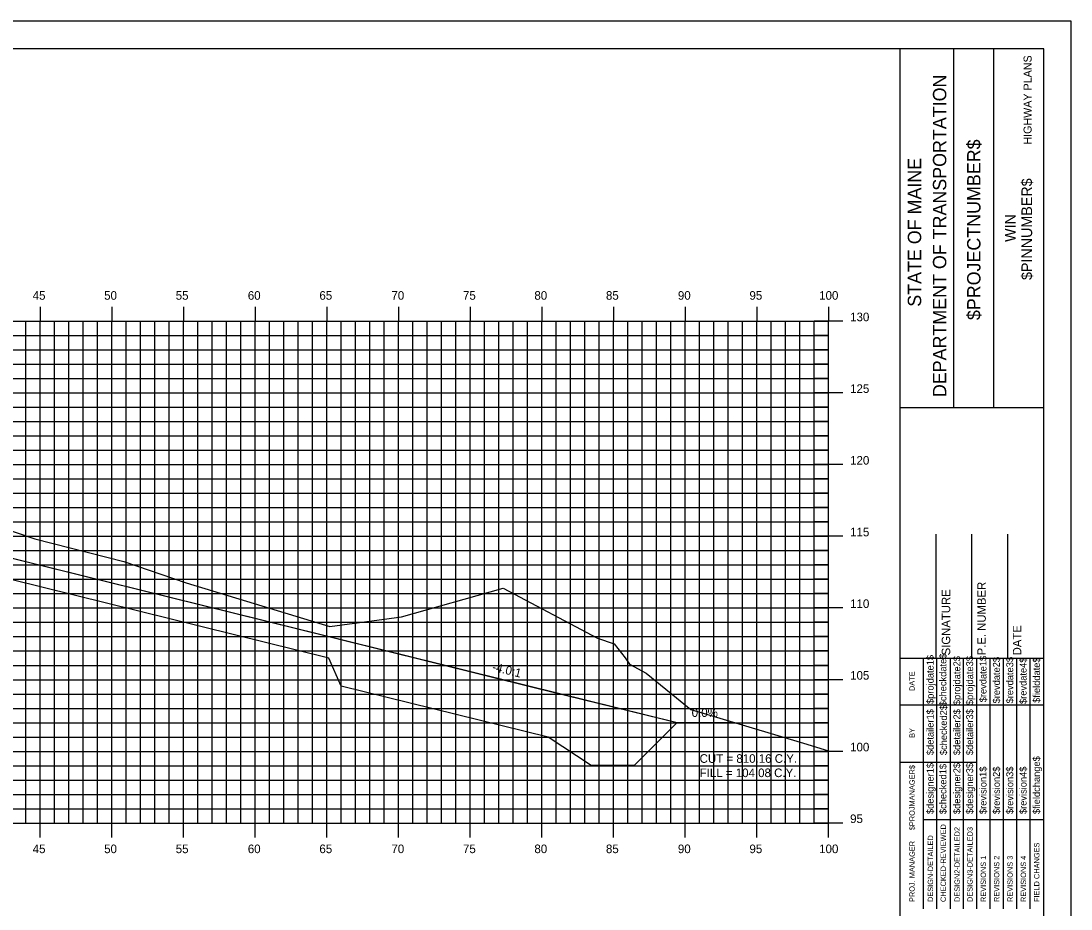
# Model space of a CAD drawing. Extents: x 850598 to 870284, y 366541 to 366651.
# Drawn here: x 859121.3 to 859194.6, y 366589.2 to 366651.2 of the extents above; entities that cross this region are included whole.
import ezdxf

# ---------------------------------------------------------------- set-up
doc = ezdxf.new("R2010")
doc.units = 0
for name, color, linetype in [('ANNOTATION', 7, 'Continuous'), ('BORDER', 7, 'Continuous'), ('D_Drainage_RipRap', 7, 'Continuous'), ('D_Roadway_Centerline', 7, 'Continuous'), ('D_Roadway_SlopeLines', 7, 'Continuous'), ('D_Text_Standard', 7, 'Continuous'), ('H_V ANNOTATION', 7, 'Continuous'), ('HIGHWAY_TITLE', 7, 'Continuous'), ('MAJOR', 7, 'Continuous'), ('MINOR', 7, 'Continuous'), ('PLOT BOUNDARY', 7, 'Continuous'), ('S_Roadway_Centerline', 7, 'Continuous')]:
    doc.layers.add(name, color=color, linetype=linetype)

msp = doc.modelspace()

# ---------------------------------------------------------------- linework, layer by layer
at = {"layer": 'BORDER'}
for p, q in [((859192.646, 366649.225), (859032.646, 366649.225)), ((859182.646, 366544.225), (859182.646, 366649.225)), ((859186.374, 366624.222), (859186.374, 366649.222)), ((859189.169, 366624.222), (859189.169, 366649.222)), ((859192.646, 366544.225), (859192.646, 366649.225)), ((859182.647, 366624.219), (859192.646, 366624.219)), ((859185.146, 366606.728), (859185.146, 366615.376)), ((859187.646, 366606.728), (859187.646, 366615.376)), ((859190.146, 366606.728), (859190.146, 366615.376)), ((859182.646, 366606.728), (859192.646, 366606.728))]:
    msp.add_line(p, q, dxfattribs=at)
for points in [[(859184.261, 366603.478), (859184.261, 366606.728)], [(859185.193, 366589.231), (859185.193, 366606.728)], [(859186.125, 366606.728), (859186.125, 366589.231)], [(859187.057, 366589.231), (859187.057, 366606.728)], [(859187.988, 366589.231), (859187.988, 366606.728)], [(859188.92, 366589.231), (859188.92, 366606.728)], [(859189.852, 366589.231), (859189.852, 366606.728)], [(859190.783, 366589.231), (859190.783, 366606.728)], [(859191.715, 366589.231), (859191.715, 366606.728)], [(859184.262, 366589.231), (859184.262, 366606.022)], [(859182.646, 366603.478), (859192.646, 366603.478)], [(859182.646, 366599.478), (859184.262, 366599.478)], [(859184.261, 366599.478), (859187.987, 366599.478)], [(859184.261, 366595.478), (859192.646, 366595.478)]]:
    msp.add_lwpolyline(points, dxfattribs=at)
at = {"layer": 'D_Drainage_RipRap'}
msp.add_lwpolyline([(859142.79, 366608.23), (859157.209, 366604.667), (859167.071, 366602.23), (859164.071, 366599.23), (859161.071, 366599.23), (859158.071, 366601.217), (859143.652, 366604.78), (859142.79, 366606.73), (859100.646, 366617.144), (859100.646, 366618.644)], close=True, dxfattribs=at)
at = {"layer": 'D_Roadway_Centerline'}
msp.add_lwpolyline([(859050.237, 366616.901), (859055.547, 366618.671), (859061.646, 366620.704), (859066.646, 366621.004), (859077.646, 366621.334), (859088.646, 366621.004), (859092.646, 366620.764), (859094.646, 366620.644), (859100.646, 366618.644), (859142.79, 366608.23), (859157.209, 366604.667), (859167.071, 366602.23), (859171.071, 366602.23)], dxfattribs=at)
at = {"layer": 'D_Roadway_SlopeLines'}
msp.add_lwpolyline([(859100.646, 366618.644), (859167.071, 366602.23), (859167.071, 366602.23)], dxfattribs=at)
at = {"layer": 'MAJOR'}
for p, q in [((859122.646, 366631.227), (859122.646, 366630.225)), ((859122.646, 366631.227), (859122.646, 366630.225)), ((859127.646, 366631.227), (859127.646, 366630.225)), ((859127.646, 366631.227), (859127.646, 366630.225)), ((859132.646, 366631.227), (859132.646, 366630.225)), ((859132.646, 366631.227), (859132.646, 366630.225)), ((859137.646, 366631.227), (859137.646, 366630.225)), ((859137.646, 366631.227), (859137.646, 366630.225)), ((859142.646, 366631.227), (859142.646, 366630.225)), ((859142.646, 366631.227), (859142.646, 366630.225)), ((859147.646, 366631.227), (859147.646, 366630.225)), ((859147.646, 366631.227), (859147.646, 366630.225)), ((859152.646, 366631.227), (859152.646, 366630.225)), ((859152.646, 366631.227), (859152.646, 366630.225)), ((859157.646, 366631.227), (859157.646, 366630.225)), ((859157.646, 366631.227), (859157.646, 366630.225)), ((859162.646, 366631.227), (859162.646, 366630.225)), ((859162.646, 366631.227), (859162.646, 366630.225)), ((859167.646, 366631.227), (859167.646, 366630.225)), ((859167.646, 366631.227), (859167.646, 366630.225)), ((859172.646, 366631.227), (859172.646, 366630.225)), ((859172.646, 366631.227), (859172.646, 366630.225)), ((859177.646, 366631.227), (859177.646, 366630.225)), ((859177.646, 366631.227), (859177.646, 366630.225)), ((859037.646, 366630.225), (859177.646, 366630.225)), ((859037.646, 366630.225), (859177.646, 366630.225)), ((859037.646, 366630.225), (859177.646, 366630.225)), ((859037.646, 366630.225), (859177.646, 366630.225)), ((859122.646, 366595.225), (859122.646, 366630.225)), ((859122.646, 366595.225), (859122.646, 366630.225)), ((859127.646, 366595.225), (859127.646, 366630.225)), ((859127.646, 366595.225), (859127.646, 366630.225)), ((859132.646, 366595.225), (859132.646, 366630.225)), ((859132.646, 366595.225), (859132.646, 366630.225)), ((859137.646, 366595.225), (859137.646, 366630.225)), ((859137.646, 366595.225), (859137.646, 366630.225)), ((859142.646, 366595.225), (859142.646, 366630.225)), ((859142.646, 366595.225), (859142.646, 366630.225)), ((859147.646, 366595.225), (859147.646, 366630.225)), ((859147.646, 366595.225), (859147.646, 366630.225)), ((859152.646, 366595.225), (859152.646, 366630.225)), ((859152.646, 366595.225), (859152.646, 366630.225)), ((859157.646, 366595.225), (859157.646, 366630.225)), ((859157.646, 366595.225), (859157.646, 366630.225)), ((859162.646, 366595.225), (859162.646, 366630.225)), ((859162.646, 366595.225), (859162.646, 366630.225)), ((859167.646, 366595.225), (859167.646, 366630.225)), ((859167.646, 366595.225), (859167.646, 366630.225)), ((859172.646, 366595.225), (859172.646, 366630.225)), ((859172.646, 366595.225), (859172.646, 366630.225)), ((859178.648, 366630.225), (859176.644, 366630.225)), ((859178.648, 366630.225), (859176.644, 366630.225)), ((859177.646, 366595.225), (859177.646, 366630.225)), ((859177.646, 366595.225), (859177.646, 366630.225)), ((859177.646, 366595.225), (859177.646, 366630.225)), ((859177.646, 366595.225), (859177.646, 366630.225)), ((859037.646, 366625.225), (859177.646, 366625.225)), ((859037.646, 366625.225), (859177.646, 366625.225)), ((859178.648, 366625.225), (859176.644, 366625.225)), ((859178.648, 366625.225), (859176.644, 366625.225)), ((859037.646, 366620.225), (859177.646, 366620.225)), ((859037.646, 366620.225), (859177.646, 366620.225)), ((859178.648, 366620.225), (859176.644, 366620.225)), ((859178.648, 366620.225), (859176.644, 366620.225)), ((859037.646, 366615.225), (859177.646, 366615.225)), ((859037.646, 366615.225), (859177.646, 366615.225)), ((859178.648, 366615.225), (859176.644, 366615.225)), ((859178.648, 366615.225), (859176.644, 366615.225)), ((859037.646, 366610.225), (859177.646, 366610.225)), ((859037.646, 366610.225), (859177.646, 366610.225)), ((859178.648, 366610.225), (859176.644, 366610.225)), ((859178.648, 366610.225), (859176.644, 366610.225)), ((859037.646, 366605.225), (859177.646, 366605.225)), ((859037.646, 366605.225), (859177.646, 366605.225)), ((859178.648, 366605.225), (859176.644, 366605.225)), ((859178.648, 366605.225), (859176.644, 366605.225)), ((859037.646, 366600.225), (859177.646, 366600.225)), ((859037.646, 366600.225), (859177.646, 366600.225)), ((859178.648, 366600.225), (859176.644, 366600.225)), ((859178.648, 366600.225), (859176.644, 366600.225)), ((859037.646, 366595.225), (859177.646, 366595.225)), ((859037.646, 366595.225), (859177.646, 366595.225)), ((859037.646, 366595.225), (859177.646, 366595.225)), ((859037.646, 366595.225), (859177.646, 366595.225)), ((859122.646, 366594.223), (859122.646, 366595.225)), ((859122.646, 366594.223), (859122.646, 366595.225)), ((859127.646, 366594.223), (859127.646, 366595.225)), ((859127.646, 366594.223), (859127.646, 366595.225)), ((859132.646, 366594.223), (859132.646, 366595.225)), ((859132.646, 366594.223), (859132.646, 366595.225)), ((859137.646, 366594.223), (859137.646, 366595.225)), ((859137.646, 366594.223), (859137.646, 366595.225)), ((859142.646, 366594.223), (859142.646, 366595.225)), ((859142.646, 366594.223), (859142.646, 366595.225)), ((859147.646, 366594.223), (859147.646, 366595.225)), ((859147.646, 366594.223), (859147.646, 366595.225)), ((859152.646, 366594.223), (859152.646, 366595.225)), ((859152.646, 366594.223), (859152.646, 366595.225)), ((859157.646, 366594.223), (859157.646, 366595.225)), ((859157.646, 366594.223), (859157.646, 366595.225)), ((859162.646, 366594.223), (859162.646, 366595.225)), ((859162.646, 366594.223), (859162.646, 366595.225)), ((859167.646, 366594.223), (859167.646, 366595.225)), ((859167.646, 366594.223), (859167.646, 366595.225)), ((859172.646, 366594.223), (859172.646, 366595.225)), ((859172.646, 366594.223), (859172.646, 366595.225)), ((859178.648, 366595.225), (859176.644, 366595.225)), ((859178.648, 366595.225), (859176.644, 366595.225)), ((859177.646, 366594.223), (859177.646, 366595.225)), ((859177.646, 366594.223), (859177.646, 366595.225))]:
    msp.add_line(p, q, dxfattribs=at)
at = {"layer": 'MINOR'}
for p, q in [((859121.646, 366595.225), (859121.646, 366630.225)), ((859121.646, 366595.225), (859121.646, 366630.225)), ((859123.646, 366595.225), (859123.646, 366630.225)), ((859123.646, 366595.225), (859123.646, 366630.225)), ((859124.646, 366595.225), (859124.646, 366630.225)), ((859124.646, 366595.225), (859124.646, 366630.225)), ((859125.646, 366595.225), (859125.646, 366630.225)), ((859125.646, 366595.225), (859125.646, 366630.225)), ((859126.646, 366595.225), (859126.646, 366630.225)), ((859126.646, 366595.225), (859126.646, 366630.225)), ((859128.646, 366595.225), (859128.646, 366630.225)), ((859128.646, 366595.225), (859128.646, 366630.225)), ((859129.646, 366595.225), (859129.646, 366630.225)), ((859129.646, 366595.225), (859129.646, 366630.225)), ((859130.646, 366595.225), (859130.646, 366630.225)), ((859130.646, 366595.225), (859130.646, 366630.225)), ((859131.646, 366595.225), (859131.646, 366630.225)), ((859131.646, 366595.225), (859131.646, 366630.225)), ((859133.646, 366595.225), (859133.646, 366630.225)), ((859133.646, 366595.225), (859133.646, 366630.225)), ((859134.646, 366595.225), (859134.646, 366630.225)), ((859134.646, 366595.225), (859134.646, 366630.225)), ((859135.646, 366595.225), (859135.646, 366630.225)), ((859135.646, 366595.225), (859135.646, 366630.225)), ((859136.646, 366595.225), (859136.646, 366630.225)), ((859136.646, 366595.225), (859136.646, 366630.225)), ((859138.646, 366595.225), (859138.646, 366630.225)), ((859138.646, 366595.225), (859138.646, 366630.225)), ((859139.646, 366595.225), (859139.646, 366630.225)), ((859139.646, 366595.225), (859139.646, 366630.225)), ((859140.646, 366595.225), (859140.646, 366630.225)), ((859140.646, 366595.225), (859140.646, 366630.225)), ((859141.646, 366595.225), (859141.646, 366630.225)), ((859141.646, 366595.225), (859141.646, 366630.225)), ((859143.646, 366595.225), (859143.646, 366630.225)), ((859143.646, 366595.225), (859143.646, 366630.225)), ((859144.646, 366595.225), (859144.646, 366630.225)), ((859144.646, 366595.225), (859144.646, 366630.225)), ((859145.646, 366595.225), (859145.646, 366630.225)), ((859145.646, 366595.225), (859145.646, 366630.225)), ((859146.646, 366595.225), (859146.646, 366630.225)), ((859146.646, 366595.225), (859146.646, 366630.225)), ((859148.646, 366595.225), (859148.646, 366630.225)), ((859148.646, 366595.225), (859148.646, 366630.225)), ((859149.646, 366595.225), (859149.646, 366630.225)), ((859149.646, 366595.225), (859149.646, 366630.225)), ((859150.646, 366595.225), (859150.646, 366630.225)), ((859150.646, 366595.225), (859150.646, 366630.225)), ((859151.646, 366595.225), (859151.646, 366630.225)), ((859151.646, 366595.225), (859151.646, 366630.225)), ((859153.646, 366595.225), (859153.646, 366630.225)), ((859153.646, 366595.225), (859153.646, 366630.225)), ((859154.646, 366595.225), (859154.646, 366630.225)), ((859154.646, 366595.225), (859154.646, 366630.225)), ((859155.646, 366595.225), (859155.646, 366630.225)), ((859155.646, 366595.225), (859155.646, 366630.225)), ((859156.646, 366595.225), (859156.646, 366630.225)), ((859156.646, 366595.225), (859156.646, 366630.225)), ((859158.646, 366595.225), (859158.646, 366630.225)), ((859158.646, 366595.225), (859158.646, 366630.225)), ((859159.646, 366595.225), (859159.646, 366630.225)), ((859159.646, 366595.225), (859159.646, 366630.225)), ((859160.646, 366595.225), (859160.646, 366630.225)), ((859160.646, 366595.225), (859160.646, 366630.225)), ((859161.646, 366595.225), (859161.646, 366630.225)), ((859161.646, 366595.225), (859161.646, 366630.225)), ((859163.646, 366595.225), (859163.646, 366630.225)), ((859163.646, 366595.225), (859163.646, 366630.225)), ((859164.646, 366595.225), (859164.646, 366630.225)), ((859164.646, 366595.225), (859164.646, 366630.225)), ((859165.646, 366595.225), (859165.646, 366630.225)), ((859165.646, 366595.225), (859165.646, 366630.225)), ((859166.646, 366595.225), (859166.646, 366630.225)), ((859166.646, 366595.225), (859166.646, 366630.225)), ((859168.646, 366595.225), (859168.646, 366630.225)), ((859168.646, 366595.225), (859168.646, 366630.225)), ((859169.646, 366595.225), (859169.646, 366630.225)), ((859169.646, 366595.225), (859169.646, 366630.225)), ((859170.646, 366595.225), (859170.646, 366630.225)), ((859170.646, 366595.225), (859170.646, 366630.225)), ((859171.646, 366595.225), (859171.646, 366630.225)), ((859171.646, 366595.225), (859171.646, 366630.225)), ((859173.646, 366595.225), (859173.646, 366630.225)), ((859173.646, 366595.225), (859173.646, 366630.225)), ((859174.646, 366595.225), (859174.646, 366630.225)), ((859174.646, 366595.225), (859174.646, 366630.225)), ((859175.646, 366595.225), (859175.646, 366630.225)), ((859175.646, 366595.225), (859175.646, 366630.225)), ((859176.646, 366595.225), (859176.646, 366630.225)), ((859176.646, 366595.225), (859176.646, 366630.225)), ((859037.646, 366629.225), (859177.646, 366629.225)), ((859037.646, 366629.225), (859177.646, 366629.225)), ((859177.646, 366629.225), (859176.644, 366629.225)), ((859177.646, 366629.225), (859176.644, 366629.225)), ((859037.646, 366628.225), (859177.646, 366628.225)), ((859037.646, 366628.225), (859177.646, 366628.225)), ((859177.646, 366628.225), (859176.644, 366628.225)), ((859177.646, 366628.225), (859176.644, 366628.225)), ((859037.646, 366627.225), (859177.646, 366627.225)), ((859037.646, 366627.225), (859177.646, 366627.225)), ((859177.646, 366627.225), (859176.644, 366627.225)), ((859177.646, 366627.225), (859176.644, 366627.225)), ((859037.646, 366626.225), (859177.646, 366626.225)), ((859037.646, 366626.225), (859177.646, 366626.225)), ((859177.646, 366626.225), (859176.644, 366626.225)), ((859177.646, 366626.225), (859176.644, 366626.225)), ((859037.646, 366624.225), (859177.646, 366624.225)), ((859037.646, 366624.225), (859177.646, 366624.225)), ((859177.646, 366624.225), (859176.644, 366624.225)), ((859177.646, 366624.225), (859176.644, 366624.225)), ((859037.646, 366623.225), (859177.646, 366623.225)), ((859037.646, 366623.225), (859177.646, 366623.225)), ((859177.646, 366623.225), (859176.644, 366623.225)), ((859177.646, 366623.225), (859176.644, 366623.225)), ((859037.646, 366622.225), (859177.646, 366622.225)), ((859037.646, 366622.225), (859177.646, 366622.225)), ((859177.646, 366622.225), (859176.644, 366622.225)), ((859177.646, 366622.225), (859176.644, 366622.225)), ((859037.646, 366621.225), (859177.646, 366621.225)), ((859037.646, 366621.225), (859177.646, 366621.225)), ((859177.646, 366621.225), (859176.644, 366621.225)), ((859177.646, 366621.225), (859176.644, 366621.225)), ((859037.646, 366619.225), (859177.646, 366619.225)), ((859037.646, 366619.225), (859177.646, 366619.225)), ((859177.646, 366619.225), (859176.644, 366619.225)), ((859177.646, 366619.225), (859176.644, 366619.225)), ((859037.646, 366618.225), (859177.646, 366618.225)), ((859037.646, 366618.225), (859177.646, 366618.225)), ((859177.646, 366618.225), (859176.644, 366618.225)), ((859177.646, 366618.225), (859176.644, 366618.225)), ((859037.646, 366617.225), (859177.646, 366617.225)), ((859037.646, 366617.225), (859177.646, 366617.225)), ((859177.646, 366617.225), (859176.644, 366617.225)), ((859177.646, 366617.225), (859176.644, 366617.225)), ((859037.646, 366616.225), (859177.646, 366616.225)), ((859037.646, 366616.225), (859177.646, 366616.225)), ((859177.646, 366616.225), (859176.644, 366616.225)), ((859177.646, 366616.225), (859176.644, 366616.225)), ((859037.646, 366614.225), (859177.646, 366614.225)), ((859037.646, 366614.225), (859177.646, 366614.225)), ((859177.646, 366614.225), (859176.644, 366614.225)), ((859177.646, 366614.225), (859176.644, 366614.225)), ((859037.646, 366613.225), (859177.646, 366613.225)), ((859037.646, 366613.225), (859177.646, 366613.225)), ((859177.646, 366613.225), (859176.644, 366613.225)), ((859177.646, 366613.225), (859176.644, 366613.225)), ((859037.646, 366612.225), (859177.646, 366612.225)), ((859037.646, 366612.225), (859177.646, 366612.225)), ((859177.646, 366612.225), (859176.644, 366612.225)), ((859177.646, 366612.225), (859176.644, 366612.225)), ((859037.646, 366611.225), (859177.646, 366611.225)), ((859037.646, 366611.225), (859177.646, 366611.225)), ((859177.646, 366611.225), (859176.644, 366611.225)), ((859177.646, 366611.225), (859176.644, 366611.225)), ((859037.646, 366609.225), (859177.646, 366609.225)), ((859037.646, 366609.225), (859177.646, 366609.225)), ((859177.646, 366609.225), (859176.644, 366609.225)), ((859177.646, 366609.225), (859176.644, 366609.225)), ((859037.646, 366608.225), (859177.646, 366608.225)), ((859037.646, 366608.225), (859177.646, 366608.225)), ((859177.646, 366608.225), (859176.644, 366608.225)), ((859177.646, 366608.225), (859176.644, 366608.225)), ((859037.646, 366607.225), (859177.646, 366607.225)), ((859037.646, 366607.225), (859177.646, 366607.225)), ((859177.646, 366607.225), (859176.644, 366607.225)), ((859177.646, 366607.225), (859176.644, 366607.225)), ((859037.646, 366606.225), (859177.646, 366606.225)), ((859037.646, 366606.225), (859177.646, 366606.225)), ((859177.646, 366606.225), (859176.644, 366606.225)), ((859177.646, 366606.225), (859176.644, 366606.225)), ((859037.646, 366604.225), (859177.646, 366604.225)), ((859037.646, 366604.225), (859177.646, 366604.225)), ((859177.646, 366604.225), (859176.644, 366604.225)), ((859177.646, 366604.225), (859176.644, 366604.225)), ((859037.646, 366603.225), (859177.646, 366603.225)), ((859037.646, 366603.225), (859177.646, 366603.225)), ((859177.646, 366603.225), (859176.644, 366603.225)), ((859177.646, 366603.225), (859176.644, 366603.225)), ((859037.646, 366602.225), (859177.646, 366602.225)), ((859037.646, 366602.225), (859177.646, 366602.225)), ((859177.646, 366602.225), (859176.644, 366602.225)), ((859177.646, 366602.225), (859176.644, 366602.225)), ((859037.646, 366601.225), (859177.646, 366601.225)), ((859037.646, 366601.225), (859177.646, 366601.225)), ((859177.646, 366601.225), (859176.644, 366601.225)), ((859177.646, 366601.225), (859176.644, 366601.225)), ((859037.646, 366599.225), (859177.646, 366599.225)), ((859037.646, 366599.225), (859177.646, 366599.225)), ((859177.646, 366599.225), (859176.644, 366599.225)), ((859177.646, 366599.225), (859176.644, 366599.225)), ((859037.646, 366598.225), (859177.646, 366598.225)), ((859037.646, 366598.225), (859177.646, 366598.225)), ((859177.646, 366598.225), (859176.644, 366598.225)), ((859177.646, 366598.225), (859176.644, 366598.225)), ((859037.646, 366597.225), (859177.646, 366597.225)), ((859037.646, 366597.225), (859177.646, 366597.225)), ((859177.646, 366597.225), (859176.644, 366597.225)), ((859177.646, 366597.225), (859176.644, 366597.225)), ((859037.646, 366596.225), (859177.646, 366596.225)), ((859037.646, 366596.225), (859177.646, 366596.225)), ((859177.646, 366596.225), (859176.644, 366596.225)), ((859177.646, 366596.225), (859176.644, 366596.225))]:
    msp.add_line(p, q, dxfattribs=at)
at = {"layer": 'PLOT BOUNDARY'}
msp.add_lwpolyline([(859024.553, 366541.166), (859194.553, 366541.166), (859194.553, 366651.166), (859024.553, 366651.166)], close=True, dxfattribs=at)
at = {"layer": 'S_Roadway_Centerline'}
msp.add_lwpolyline([(859110.249, 366619.114), (859122.268, 366615.044), (859128.488, 366613.457), (859132.828, 366611.97), (859142.856, 366608.936), (859147.847, 366609.603), (859154.933, 366611.613), (859161.524, 366608.115), (859162.686, 366607.733), (859163.463, 366606.752), (859163.752, 366606.318), (859164.925, 366605.673), (859168.031, 366603.134), (859175.889, 366600.797), (859177.646, 366600.261)], dxfattribs=at)

# ---------------------------------------------------------------- texts
at = {"layer": 'ANNOTATION'}
msp.add_text('-4.0:1', height=0.6, rotation=346.11922, dxfattribs=at).set_placement((859154.137, 366605.856))
msp.add_text('0.0%', height=0.6, dxfattribs=at).set_placement((859168.092, 366602.625))
at = {"layer": 'BORDER'}
for s, height, p in [('DEPARTMENT OF TRANSPORTATION', 0.93176, (859185.853, 366624.931)), ('$PROJECTNUMBER$', 0.93176, (859188.238, 366630.304)), ('STATE OF MAINE', 0.93176, (859184.101, 366631.237)), ('$PINNUMBER$', 0.74527, (859191.841, 366633.1)), ('WIN', 0.7453, (859190.683, 366635.755)), ('P.E. NUMBER', 0.59055, (859188.607, 366606.92)), ('SIGNATURE', 0.5906, (859186.126, 366606.92)), ('DATE', 0.5906, (859191.087, 366606.92)), ('$projdate1$', 0.48455, (859184.969, 366603.529)), ('$checkdate$', 0.48455, (859185.863, 366603.371)), ('$projdate2$', 0.48455, (859186.832, 366603.45)), ('$projdate3$', 0.48455, (859187.727, 366603.45)), ('$revdate1$', 0.4845, (859188.658, 366603.647)), ('$revdate2$', 0.4845, (859189.59, 366603.568)), ('$revdate3$', 0.4845, (859190.522, 366603.568)), ('$revdate4$', 0.4845, (859191.453, 366603.529)), ('$fielddate$', 0.48455, (859192.385, 366603.607)), ('DATE', 0.3714, (859183.65, 366604.434)), ('$detailer1$', 0.48455, (859184.969, 366599.963)), ('$checked2$', 0.4845, (859185.9, 366599.963)), ('$detailer2$', 0.48455, (859186.832, 366599.963)), ('$detailer3$', 0.48455, (859187.727, 366599.963)), ('BY', 0.3714, (859183.65, 366601.163)), ('$fieldchange$', 0.48455, (859192.385, 366595.851)), ('$PROJMANAGER$', 0.37275, (859183.65, 366594.723)), ('$designer1$', 0.48455, (859184.969, 366595.851)), ('$checked1$', 0.4845, (859185.863, 366595.851)), ('$designer2$', 0.48455, (859186.832, 366595.851)), ('$designer3$', 0.48455, (859187.727, 366595.851)), ('$revision1$', 0.48455, (859188.658, 366595.851)), ('$revision2$', 0.48455, (859189.59, 366595.851)), ('$revision3$', 0.48455, (859190.522, 366595.851)), ('$revision4$', 0.48455, (859191.453, 366595.851)), ('CHECKED-REVIEWED', 0.37275, (859185.827, 366589.716)), ('DESIGN2-DETAILED2', 0.37275, (859186.796, 366589.716)), ('DESIGN3-DETAILED3', 0.37275, (859187.69, 366589.716)), ('PROJ. MANAGER', 0.37275, (859183.65, 366589.716)), ('DESIGN-DETAILED', 0.37275, (859184.932, 366589.716)), ('FIELD CHANGES', 0.37275, (859192.349, 366589.716)), ('REVISIONS 1', 0.37275, (859188.622, 366589.716)), ('REVISIONS 2', 0.37275, (859189.554, 366589.716)), ('REVISIONS 3', 0.37275, (859190.485, 366589.716)), ('REVISIONS 4', 0.37275, (859191.417, 366589.716))]:
    msp.add_text(s, height=height, rotation=90, dxfattribs=at).set_placement(p)
at = {"layer": 'D_Text_Standard'}
for s, p in [('CUT = 810.16 C.Y.', (859168.646, 366599.425)), ('FILL = 104.08 C.Y.', (859168.646, 366598.429))]:
    msp.add_text(s, height=0.6, dxfattribs=at).set_placement(p)
at = {"layer": 'H_V ANNOTATION'}
for s, p in [('45', (859122.124, 366631.725)), ('50', (859127.11, 366631.725)), ('55', (859132.102, 366631.725)), ('60', (859137.132, 366631.725)), ('65', (859142.124, 366631.725)), ('70', (859147.148, 366631.725)), ('75', (859152.14, 366631.725)), ('80', (859157.121, 366631.725)), ('85', (859162.113, 366631.725)), ('90', (859167.132, 366631.725)), ('95', (859172.124, 366631.725)), ('100', (859176.987, 366631.725)), ('130', (859179.146, 366630.225)), ('125', (859179.146, 366625.225)), ('120', (859179.146, 366620.225)), ('115', (859179.146, 366615.225)), ('110', (859179.146, 366610.225)), ('105', (859179.146, 366605.225)), ('100', (859179.146, 366600.225)), ('95', (859179.146, 366595.225)), ('45', (859122.124, 366593.125)), ('50', (859127.11, 366593.125)), ('55', (859132.102, 366593.125)), ('60', (859137.132, 366593.125)), ('65', (859142.124, 366593.125)), ('70', (859147.148, 366593.125)), ('75', (859152.14, 366593.125)), ('80', (859157.121, 366593.125)), ('85', (859162.113, 366593.125)), ('90', (859167.132, 366593.125)), ('95', (859172.124, 366593.125)), ('100', (859176.987, 366593.125))]:
    msp.add_text(s, height=0.6, dxfattribs=at).set_placement(p)
at = {"layer": 'HIGHWAY_TITLE'}
msp.add_text('HIGHWAY PLANS', height=0.55901, rotation=90, dxfattribs=at).set_placement((859191.804, 366642.541))

doc.saveas('drawing.dxf')
